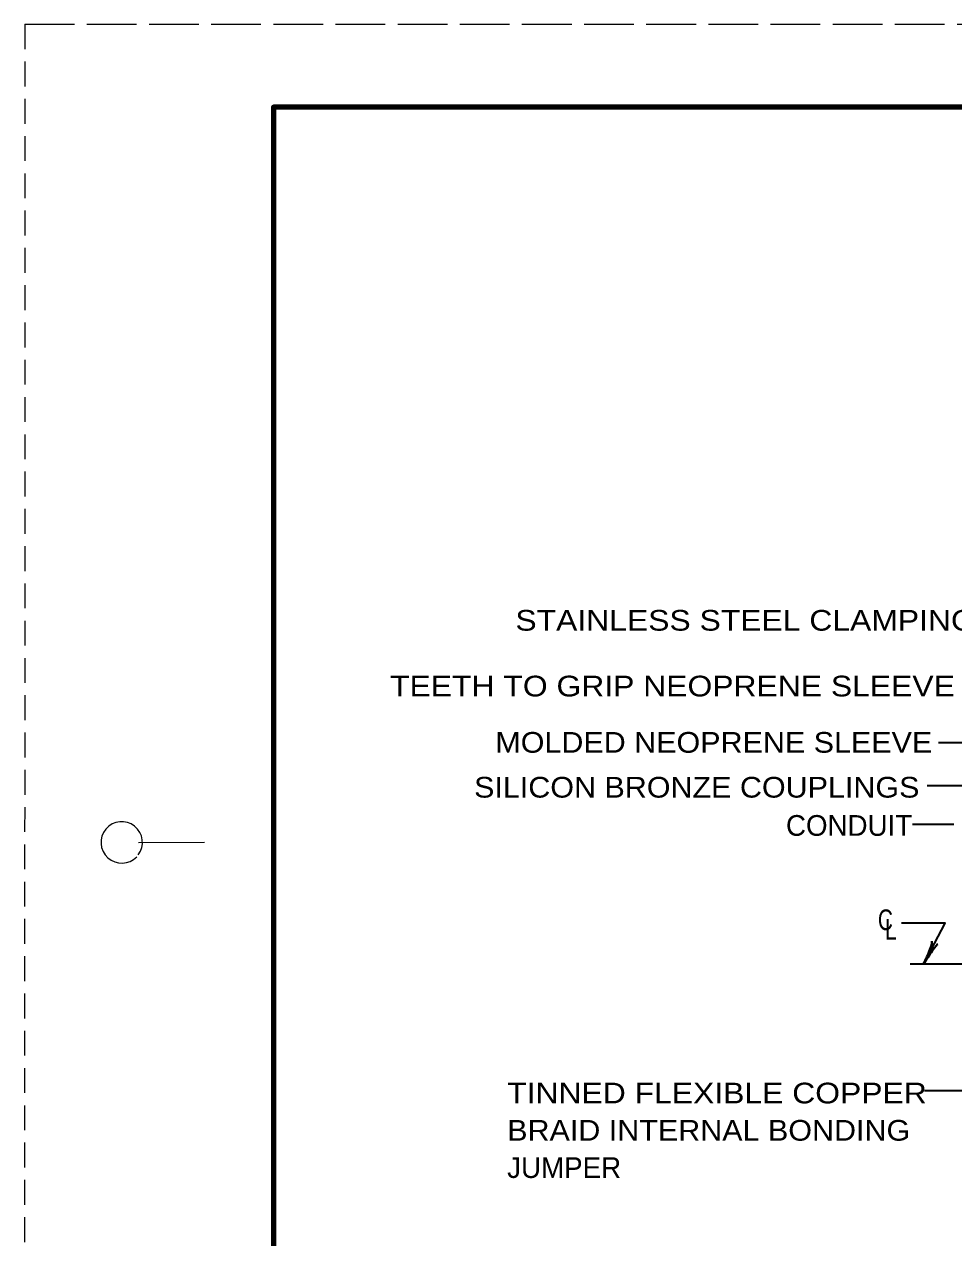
# Model space of a CAD drawing. Extents: x -1 to 679, y 0 to 440.
# Drawn here: x -1.4 to 110.7, y 293.3 to 439.8 of the extents above; entities that cross this region are included whole.
import ezdxf

# ---------------------------------------------------------------- set-up
doc = ezdxf.new("R2010")
doc.units = 0
doc.linetypes.add('LONG_DASHED', pattern=[7.5, 6, -1.5])
doc.linetypes.add('MEDIUM_DASHED', pattern=[4.5, 3, -1.5])
doc.layers.add('1', color=7, linetype='Continuous', lineweight=35)
doc.layers.add('61', color=7, linetype='Continuous', lineweight=35)

msp = doc.modelspace()

# ---------------------------------------------------------------- linework, layer by layer
at = {"layer": '1', "linetype": 'MEDIUM_DASHED', "lineweight": 13}
msp.add_line((-1.376, 439.785), (-1.436, -0.255), dxfattribs=at)
at = {"layer": '1'}
for p, q in [((108.894, 353.095), (113.894, 353.095)), ((107.504, 347.899), (112.504, 347.899)), ((105.748, 343.214), (110.748, 343.214)), ((122.976, 311.023), (107.209, 311.023))]:
    msp.add_line(p, q, dxfattribs=at)
for points in [[(107.104, 326.376), (109.706, 331.292), (104.426, 331.292)], [(105.463, 326.376), (126.934, 326.376), (132.463, 326.376)]]:
    msp.add_lwpolyline(points, dxfattribs=at)
at = {"layer": '1', "lineweight": 40}
for centre, major_axis, ratio, start_param, end_param in [((107.37, 327.47), (-0.697, -1.651), 0.122415, 0.8963533, 3.1415927), ((107.37, 327.47), (-0.697, -1.651), 0.122415, 0.8963533, 3.1415927), ((107.815, 327.267), (-0.977, -1.47), 0.07063, 3.1407148, 5.41811), ((107.815, 327.267), (-0.977, -1.47), 0.07063, 3.1407148, 5.41811)]:
    msp.add_ellipse(centre, major_axis=major_axis, ratio=ratio, start_param=start_param, end_param=end_param, dxfattribs=at)
at = {"layer": '61', "linetype": 'LONG_DASHED', "lineweight": 13}
msp.add_line((-1.376, 439.785), (678.644, 439.785), dxfattribs=at)
at = {"layer": '61', "lineweight": 13}
msp.add_line((12.344, 341.025), (20.324, 341.045), dxfattribs=at)
at = {"layer": '61', "lineweight": 158}
msp.add_lwpolyline([(667.664, 429.785), (28.624, 429.785), (28.624, 9.765)], dxfattribs=at)
at = {"layer": '61', "lineweight": 13}
msp.add_arc((10.321, 341.026), 2.5, 323.13009, 316.23216, dxfattribs=at)

# ---------------------------------------------------------------- texts
at = {"layer": '1'}
for s, width, p in [('STAINLESS STEEL CLAMPING BANDS', 1.15, (57.827, 366.586)), ('TEETH TO GRIP NEOPRENE SLEEVE', 1.15, (42.709, 358.649)), ('MOLDED NEOPRENE SLEEVE', 1.1, (55.406, 351.852)), ('SILICON BRONZE COUPLINGS', 1.1, (52.842, 346.436)), ('C', 0.75, (101.572, 330.435)), ('L', 0.75, (102.428, 329.294)), ('TINNED FLEXIBLE COPPER', 1.15, (56.838, 309.522)), ('BRAID INTERNAL BONDING', 1.1, (56.838, 305.022))]:
    msp.add_text(s, height=2.5, dxfattribs=dict(at, width=width)).set_placement(p)
for s, p in [('CONDUIT', (90.48, 341.824)), ('JUMPER', (56.838, 300.522))]:
    msp.add_text(s, height=2.5, dxfattribs=at).set_placement(p)

doc.saveas('drawing.dxf')
